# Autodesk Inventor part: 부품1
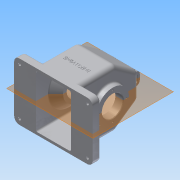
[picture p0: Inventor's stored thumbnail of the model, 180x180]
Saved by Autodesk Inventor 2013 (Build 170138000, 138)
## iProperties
Created: 2016-12
Part Number: 부품1
Material: 알루미늄 6061
Document SubType Name: Modeling
Designer: Administrator
Density: 2.71 g/cm^3
Mass: 1063.77 g
Surface Area: 1146.35 cm^2
Volume: 392.536 cm^3
Author: Administrator
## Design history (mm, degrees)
sketch "스케치2"
  geometry: L1 (-75, -55)-(75, -55); L2 (75, -55)-(75, 55); L3 (75, 55)-(-75, 55); L4 (-75, 55)-(-75, -55); L5 (-75, -55)-(75, 55); L6 (75, -55)-(-75, 55); 1 further point
  constraints: 12 end point, 2 midpoint, 2 parallel, 1 horizontal, 1 perpendicular
  dimensions: "d0" = 150 distance of L2.end L3.end; "d2" = 110 distance of L1.end L2.end
extrude "돌출1" new body sketch "스케치2" distance "d3" = 15; taper "d4" = 0 deg
fillet "모깎기1" dims "d5" = 10
hole "구멍1" diameter "d8" = 5; stored, may be unused: countersink angle "d12" = 90 deg, drill point angle "d14" = 118 deg; dims "d6" = 10, "d7" = 10, "d9" = 6, "d10" = 12, "d11" = 5, "d13" = 8
node "작업 평면1"
sketch "스케치4"
  geometry: L1 (100, 0)-(-10, 0) reference; L2 (-10, 0)-(-10, 15) reference; L3 (-10, 15)-(100, 15) reference; L4 (100, 15)-(100, 0) reference; L5 (-10, 15)-(-10, 80); L6 (-10, 80)-(21.509, 125); L7 (21.509, 125)-(68.491, 125); L8 (68.491, 125)-(100, 80); L9 (100, 80)-(100, 15); L10 (-10, 15)-(100, 15); 3 further points
  constraints: 12 end point, 2 midpoint, 1 collinear, 1 parallel, 1 perpendicular, 1 point on line, 1 vertical, 1 vertical alignment
  dimensions: "d22" = 35 deg angle of L6 L5; "d23" = 35 deg angle of L9 L8; "d24" = 80 distance of L1.start L8.end; "d25" = 125 distance between parallel lines of L1 L7
extrude "돌출2" join sketch "스케치4" stored distance "d26" = 77; taper "d27" = 0 deg
node "작업 평면2"
sketch "스케치5"
  geometry: L1 (-10, 80)-(21.509, 125) reference; L2 (21.509, 125)-(68.491, 125) reference; L3 (68.491, 125)-(100, 80) reference; L4 (100, 80)-(100, 0) reference; L5 (100, 0)-(-10, 0) reference; L6 (-10, 0)-(-10, 80) reference; L7 (65.888, 120)-(24.112, 120); L8 (24.112, 120)-(-5, 78.424); L9 (-5, 78.424)-(-5, 0); L10 (95, 0)-(95, 78.424); L11 (95, 78.424)-(65.888, 120); L12 (-5, 0)-(95, 0); 1 further point
  constraints: 12 end point, 2 point on line, 1 collinear, 1 other
  dimensions: "d28" = 5 distance between parallel lines of L2 L7; "d29" = 78.42351 distance of L8.end L9.end; "d30" = 50.75553 distance of L7.end L8.end; "d31" = 41.77565 distance of L7.start L7.end; "d32" = 29.11217 horizontal distance of L10.end L7.start; "d33" = 78.42351 distance of L10.start L10.end; "d34" = 100 distance of L10.start L9.end
extrude "돌출3" cut sketch "스케치5" stored distance "d35" = 67; taper "d36" = 0 deg
sketch "스케치6"
  geometry: L1 (-30.313, 65)-(120.313, 65); L2 (0, 0)-(90, 0) reference; C1 r 37.5 at (45, 65); 3 further points
  constraints: 2 end point, 2 midpoint, 1 centre point, 1 coincident, 1 horizontal, 1 vertical alignment
  dimensions: "d38" = 65 distance from line of L1.end L2; "d39" = 150.62512 distance of L1.start L1.end; "d40" = 75 diameter of C1
extrude "돌출4" join sketch "스케치6" distance "d41" = 5; taper "d42" = 0 deg
sketch "스케치7"
  geometry: L1 (-90, 0)-(0, 0) reference; C1 r 31 at (-45, 65); 2 further points
  constraints: 1 centre point, 1 midpoint, 1 vertical alignment
  dimensions: "d43" = 65 distance from line of C1.centre L1; "d44" = 62 diameter of C1
extrude "돌출5" join sketch "스케치7" distance "d45" = 10; taper "d46" = 0 deg
sketch "스케치8"
  geometry: L1 (-43.5, 102.5)-(-43.5, 27.5) reference; L2 (-19.5, 92)-(-19.5, 65); L3 (-19.5, 92)-(-33.5, 106); L4 (-33.5, 78.424)-(-33.5, 0) reference; L5 (-33.5, 65)-(-33.5, 106); L6 (-43.5, 65)-(48.5, 65); L7 (-33.5, 65)-(-19.5, 65); 1 further point
  constraints: 10 end point, 1 midpoint, 1 perpendicular, 1 point on line
  dimensions: "d49" = 24 distance between parallel lines of L2 L1; "d50" = 45 deg angle of L2 L3; "d53" = 41 distance of L5.start L3.end; "d54" = 14 horizontal distance of L2.start L3.end; "d55" = 92 distance of L6.start L6.end; "d56" = 54 diameter of L2.start L6; "d57" = 27 distance of L2.start L2.end
revolve "회전1" sketch "스케치8" stored, may be unused: angle "d58" = 90 deg
sketch "스케치9"
  geometry: C1 r 31 at (0, 0) reference; C2 r 20 at (0, 0); 1 further point
  constraints: 1 centre point, 1 coincident
  dimensions: "d59" = 40 diameter of C2
extrude "돌출6" cut sketch "스케치9" stored distance "d61" = 10; taper "d62" = 0 deg
sketch "스케치10"
  geometry: C1 r 20 at (0, 0) reference; 2 further points
  constraints: 1 vertical alignment
  dimensions: "d63" = 29 distance of C1.centre point (0, 29)
hole "구멍2" sketch "스케치10" at (0, 29) diameter "d64" = 2.459; stored, may be unused: countersink angle "d68" = 90 deg, drill point angle "d70" = 118 deg; dims "d65" = 6, "d66" = 12, "d67" = 5, "d69" = 8
sketch "스케치11"
  geometry: C1 r 20 at (0, 0) reference; 2 further points
  constraints: 1 vertical alignment
  dimensions: "d74" = 26 distance of point (0, 26) C1.centre
hole "구멍3" sketch "스케치11" at (0, 26) diameter "d75" = 2.459; stored, may be unused: countersink angle "d79" = 90 deg, drill point angle "d81" = 118 deg; dims "d76" = 6, "d77" = 12, "d78" = 5, "d80" = 8
node "작업 평면4"
sketch "스케치13"
  geometry: L1 (125, 23.491)-(125, -23.491) reference; L2 (125, 12.5)-(140, 12.5); L3 (140, 12.5)-(140, -12.5); L4 (140, -12.5)-(125, -12.5); L5 (125, -7.5)-(135, -7.5); L6 (135, -7.5)-(135, 7.5); L7 (135, 7.5)-(125, 7.5); L8 (125, 12.5)-(125, 7.5); L9 (125, -7.5)-(125, -12.5); 2 further points
  constraints: 16 end point, 4 perpendicular, 2 point on line, 1 horizontal alignment, 1 midpoint, 2 other
  dimensions: "d93" = 140 distance from line of point (0, 0) L3; "d94" = 25 distance of L2.end L3.end; "d95" = 5 distance between parallel lines of L4 L5; "d96" = 10 distance of L6.end L7.end; "d97" = 10 distance of L5.start L5.end
extrude "돌출7" join sketch "스케치13" distance "d98" = 8; taper "d99" = 0 deg
fillet "모깎기3" dims "d100" = 8
fillet "모깎기5" dims "d102" = 1
fillet "모깎기8" dims "d105" = 3
fillet "모깎기9" dims "d106" = 8
fillet "모깎기10" dims "d107" = 10
fillet "모깎기11" dims "d108" = 3
sketch "스케치14"
  geometry: L1 (26.5, 76.847)-(26.5, 18) reference; L2 (0, 0)-(130, 0) reference; 2 further points
  constraints: 1 other
  dimensions: "d109" = 38.5 horizontal distance of point (65, 45) L1.end; "d110" = 45 distance from line of point (65, 45) L2
feature "엠보싱1" sketch "스케치14" dims "d111" = 0.5, "d112" = 0
fillet "모깎기12" dims "d113" = 3, "d114" = 3
fillet "모깎기13" dims "d115" = 1
fillet "모깎기14" dims "d116" = 1
fillet "모깎기15" dims "d117" = 3
chamfer "모따기1" distance "d118" = 1; stored, may be unused: second distance "d119" = 2, angle "d120" = 45 deg
fillet "모깎기21" dims "d126" = 3
node "솔리드1"
mirror "대칭1"
mirror "대칭2"
pattern_circular "원형 패턴1" dims angle "d72" = 360 deg
pattern_circular "원형 패턴2" dims angle "d83" = 360 deg
mirror "대칭3"
node "절단 모서리 투영1"
node "절단 모서리 투영2"
other parameters: "d16" = -75, "d92" = 18
